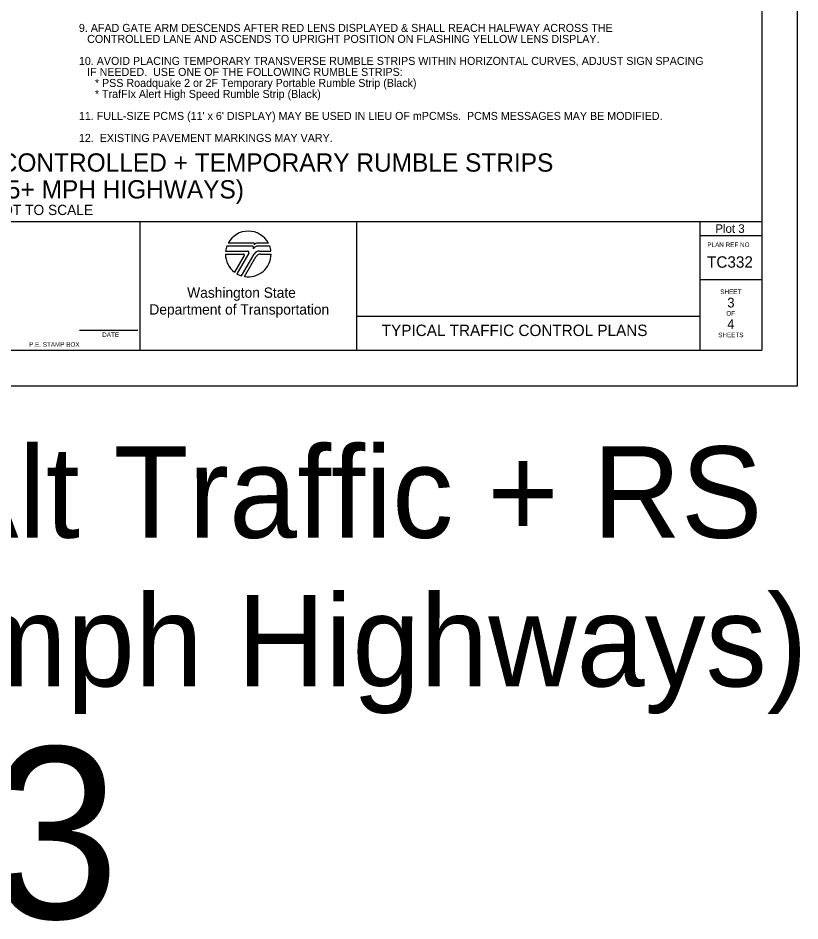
# Model space of a CAD drawing. Extents: x 99999.1 to 100095.7, y 99995 to 100010.7.
# Drawn here: x 100049.24 to 100056.08, y 99995.01 to 100002.9 of the extents above; entities that cross this region are included whole.
import ezdxf

# ---------------------------------------------------------------- set-up
doc = ezdxf.new("R2010")
doc.units = 0
for name, color, linetype in [('SH_DE_DetailHeading1Text', 7, 'Continuous'), ('SH_GI_GeneralNotesBodyText', 7, 'Continuous'), ('SH_GI_PlotLimits', 7, 'Continuous'), ('SH_GI_SheetBorder', 7, 'Continuous'), ('SH_GI_SheetLocationText', 7, 'Continuous'), ('SH_GI_SheetTextInCells', 7, 'Continuous'), ('SH_GI_TitleBlockText', 7, 'Continuous'), ('SH_GI_WSDOTLogo', 7, 'Continuous')]:
    doc.layers.add(name, color=color, linetype=linetype)

msp = doc.modelspace()

# ---------------------------------------------------------------- linework, layer by layer
at = {"layer": 'SH_GI_PlotLimits'}
msp.add_lwpolyline([(100039.0625, 99999.6875), (100056.0625, 99999.6875), (100056.0625, 100010.6875), (100039.0625, 100010.6875)], close=True, dxfattribs=at)
at = {"layer": 'SH_GI_SheetBorder'}
for p, q in [((100055.75, 100010.375), (100055.75, 100000)), ((100040, 100001.1259), (100055.75, 100001.1259)), ((100050.3089, 100001.1259), (100050.3089, 100000)), ((100052.2055, 100001.1259), (100052.2055, 100000)), ((100055.2079, 100001.1259), (100055.2079, 100000)), ((100055.2079, 100001.0008), (100055.75, 100001.0008)), ((100055.2079, 100000.6176), (100055.75, 100000.6176)), ((100052.2055, 100000.2955), (100055.2079, 100000.2955)), ((100049.7797, 100000.1733), (100050.2914, 100000.1733)), ((100040, 100000), (100055.75, 100000))]:
    msp.add_line(p, q, dxfattribs=at)
at = {"layer": 'SH_GI_WSDOTLogo'}
for p, q in [((100051.303, 100000.9354), (100051.0815, 100000.9354)), ((100051.433, 100000.9354), (100051.3351, 100000.9354)), ((100051.0572, 100000.84), (100051.2148, 100000.84)), ((100051.059, 100000.8661), (100051.2496, 100000.8661)), ((100051.2894, 100000.9094), (100051.0697, 100000.9094)), ((100051.261, 100000.8464), (100051.1567, 100000.6672)), ((100051.1989, 100000.6487), (100051.3089, 100000.839)), ((100051.343, 100000.9094), (100051.3429, 100000.9094)), ((100051.4448, 100000.9094), (100051.343, 100000.9094)), ((100051.3558, 100000.8661), (100051.4555, 100000.8661)), ((100051.3655, 100000.8394), (100051.4572, 100000.8394)), ((100051.222, 100000.8277), (100051.1364, 100000.6807)), ((100051.2244, 100000.6428), (100051.3242, 100000.8156))]:
    msp.add_line(p, q, dxfattribs=at)
for centre, radius, start, end in [((100051.2572, 100000.84), 0.2, 28.47865, 151.53204), ((100051.303, 100000.9263), 0.00903, 329.87418, 90.00328), ((100051.3352, 100000.9066), 0.0287, 90.00721, 148.16763), ((100051.2572, 100000.84), 0.2, 179.99864, 232.84327), ((100051.2572, 100000.84), 0.2, 159.69598, 172.50569), ((100051.2149, 100000.8318), 0.0082, 329.74356, 90), ((100051.2572, 100000.84), 0.2, 260.54554, 359.80857), ((100051.2497, 100000.853), 0.0131, 329.76834, 90), ((100051.2894, 100000.8946), 0.0148, 327.8418, 89.99855), ((100051.3429, 100000.861), 0.0484, 89.99529, 147.82376), ((100051.3558, 100000.8119), 0.0542, 90, 149.99738), ((100051.3654, 100000.7918), 0.0476, 90, 150.05432), ((100051.2572, 100000.84), 0.2, 7.49431, 20.29406), ((100051.2572, 100000.84), 0.2, 239.79292, 253.0448)]:
    msp.add_arc(centre, radius, start, end, dxfattribs=at)

# ---------------------------------------------------------------- texts
at = {"layer": 'SH_DE_DetailHeading1Text'}
for s, height, p in [('ALTERNATING 1-LANE, 2-WAY TRAFFIC: AFAD-CONTROLLED + TEMPORARY RUMBLE STRIPS', 0.16, (100044.2559, 100001.5606)), ('(HIGH VOLUME 45+ MPH HIGHWAYS)', 0.16, (100047.3973, 100001.3259)), ('NOT TO SCALE', 0.09, (100049.0168, 100001.1809))]:
    msp.add_text(s, height=height, rotation=360, dxfattribs=at).set_placement(p)
at = {"layer": 'SH_GI_GeneralNotesBodyText'}
for s, p in [('9. AFAD GATE ARM DESCENDS AFTER RED LENS DISPLAYED & SHALL REACH HALFWAY ACROSS THE ', (100049.7751, 100002.7831)), ('CONTROLLED LANE AND ASCENDS TO UPRIGHT POSITION ON FLASHING YELLOW LENS DISPLAY.', (100049.8473, 100002.6868)), ('10. AVOID PLACING TEMPORARY TRANSVERSE RUMBLE STRIPS WITHIN HORIZONTAL CURVES, ADJUST SIGN SPACING ', (100049.7751, 100002.4943)), ('IF NEEDED.  USE ONE OF THE FOLLOWING RUMBLE STRIPS:', (100049.8473, 100002.3981)), ('* PSS Roadquake 2 or 2F Temporary Portable Rumble Strip (Black)', (100049.9151, 100002.3018)), ('* TrafFIx Alert High Speed Rumble Strip (Black)', (100049.9151, 100002.2056)), ("11. FULL-SIZE PCMS (11' x 6' DISPLAY) MAY BE USED IN LIEU OF mPCMSs.  PCMS MESSAGES MAY BE MODIFIED.", (100049.7751, 100002.0131)), ('12.  EXISTING PAVEMENT MARKINGS MAY VARY.', (100049.7751, 100001.8206))]:
    msp.add_text(s, height=0.07, rotation=360, dxfattribs=at).set_placement(p)
at = {"layer": 'SH_GI_SheetBorder'}
msp.add_text('PLAN REF NO', height=0.040032, dxfattribs=at).set_placement((100055.2747, 100000.9008))
at = {"layer": 'SH_GI_SheetLocationText'}
for s, height, p in [('Plot 3', 0.075, (100055.3447, 100001.025)), ('AFAD-Controlled Alt Traffic + RS', 0.8, (100040.1515, 99998.3571)), ('(High-Volume 45+ mph Highways)', 0.8, (100039.8302, 99997.0571)), ('Plot 3', 1.5, (100045.0008, 99995.0267))]:
    msp.add_text(s, height=height, dxfattribs=at).set_placement(p)
at = {"layer": 'SH_GI_SheetTextInCells'}
for s, height, p in [('Washington State', 0.090072, (100050.7229, 100000.4571)), ('SHEET', 0.04003, (100055.3877, 100000.4896)), ('Department of Transportation', 0.090072, (100050.3916, 100000.3101)), ('OF', 0.04003, (100055.4406, 100000.3008)), ('DATE', 0.04003, (100049.9794, 100000.1141)), ('SHEETS', 0.04003, (100055.3698, 100000.112)), ('P.E. STAMP BOX', 0.040032, (100049.339, 100000.0286))]:
    msp.add_text(s, height=height, dxfattribs=at).set_placement(p)
at = {"layer": 'SH_GI_TitleBlockText'}
for s, height, p in [('TC332', 0.1, (100055.2718, 100000.72)), ('3', 0.085, (100055.4493, 100000.3723)), ('TYPICAL TRAFFIC CONTROL PLANS', 0.1, (100052.4251, 100000.1224)), ('4', 0.085, (100055.4485, 100000.1843))]:
    msp.add_text(s, height=height, dxfattribs=at).set_placement(p)

doc.saveas('drawing.dxf')
